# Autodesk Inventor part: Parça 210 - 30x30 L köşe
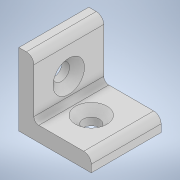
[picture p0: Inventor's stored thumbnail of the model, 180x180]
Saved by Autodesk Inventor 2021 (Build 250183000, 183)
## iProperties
Created: 2026-05
Part Number: Parça 210 - 30x30 L köşe
Material: Generic
Description: STEP AP203
Document SubType Name: Modeling
Designer: hp
Density: 1 g/cm^3
Appearance: Default
Sending System: SolidWorks 2024
Preprocessor: SwSTEP 2.0
Title: Parça 210 - 30x30 L köþe.step
Revision Number: ANY
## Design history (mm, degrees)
feature "CSK for M6 Countersunk Flat Head Screw2"
body "Solid1"
